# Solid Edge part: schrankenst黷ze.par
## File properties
Author: Wir
Template: Normal.par
Last saved by: Wir
Revision: 1
Application: Solid Edge
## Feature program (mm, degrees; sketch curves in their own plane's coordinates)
sketch for "unnamed Protrusion 1" plane through (0, 0, 0) normal (0, 0, 1) x-axis (1, 0, 0)
extrude "unnamed Protrusion 1" add finite 60 along +normal
sketch for "unnamed Cutout 1" plane through (2.5, 0, 30) normal (1, 0, 0) x-axis (0, 0, 1)
extrude "unnamed Cutout 1" cut finite 114.3 symmetric
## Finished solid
Body 1: solid body, 7 faces, 14 edges, 8 vertices.
  Faces by surface: plane 6, cylinder 1
  Edges by curve: line 12, circle 2
Bounding box of the edges (mm): 5.000 x 10.000 x 60.000, from (-2.5, -5, 0) to (2.5, 5, 60).
Cylindrical faces by radius (mm): R2.5 x1
Planar faces by outward normal: +x 1, +y 1, +z 1, -x 1, -y 1, -z 1
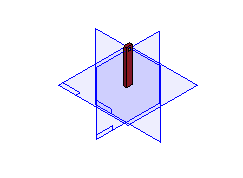
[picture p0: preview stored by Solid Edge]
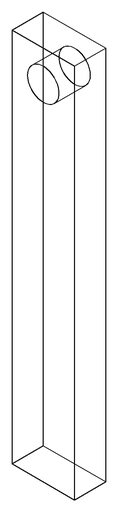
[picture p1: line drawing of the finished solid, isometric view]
